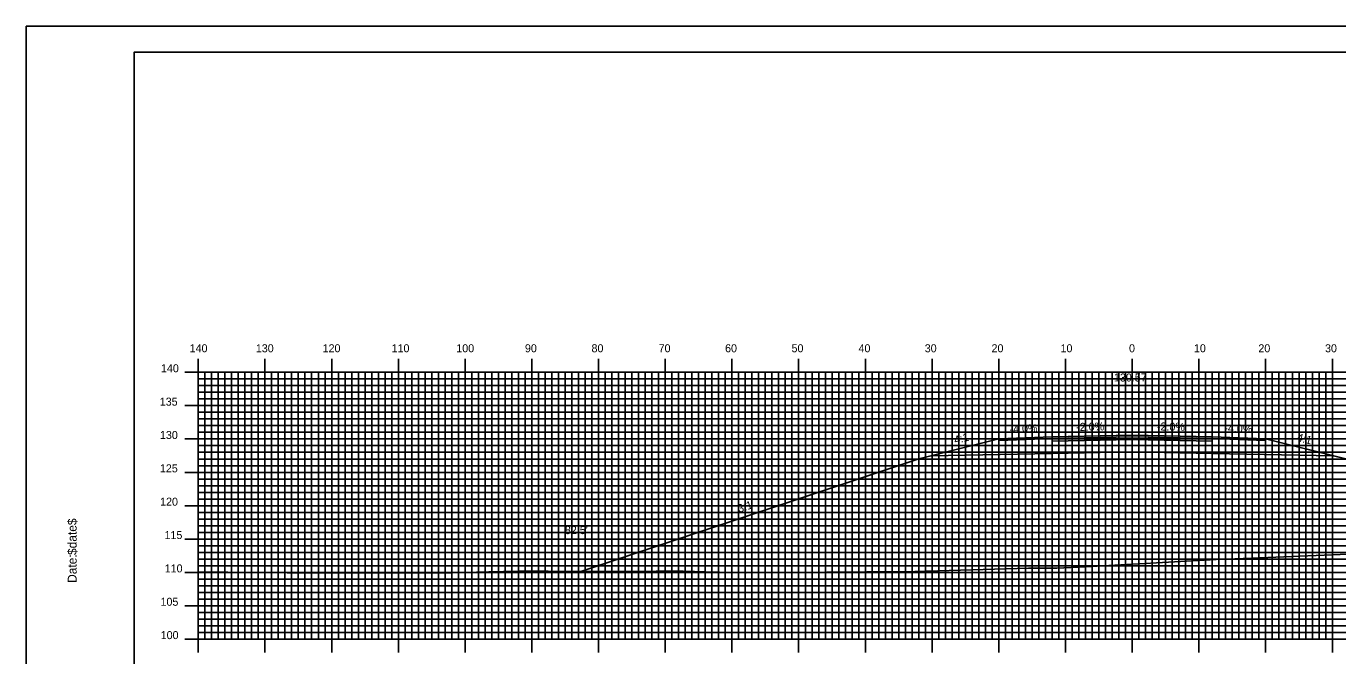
# Model space of a CAD drawing. Extents: x 1781860 to 1782203, y 442591 to 442811.
# Drawn here: x 1781860.1 to 1782056.7, y 442716.2 to 442810.5 of the extents above; entities that cross this region are included whole.
import ezdxf

# ---------------------------------------------------------------- set-up
doc = ezdxf.new("R2010")
doc.units = 0
for name, color, linetype in [('ANNOTATION', 7, 'Continuous'), ('BORDER', 7, 'Continuous'), ('D_Roadway_Centerline', 7, 'Continuous'), ('D_Roadway_Centerline_Text', 7, 'Continuous'), ('D_Roadway_Edge_Shoulder', 7, 'Continuous'), ('D_Roadway_Edge_TW', 7, 'Continuous'), ('D_Roadway_Pavement', 7, 'Continuous'), ('D_Roadway_SlopeLines', 7, 'Continuous'), ('D_Roadway_SubGrade', 7, 'Continuous'), ('D_Text_Standard', 7, 'Continuous'), ('H_V ANNOTATION', 7, 'Continuous'), ('MAJOR', 7, 'Continuous'), ('MINOR', 7, 'Continuous'), ('PLOT BOUNDARY', 7, 'Continuous'), ('S_Roadway_Centerline', 7, 'Continuous')]:
    doc.layers.add(name, color=color, linetype=linetype)

msp = doc.modelspace()

# ---------------------------------------------------------------- linework, layer by layer
at = {"layer": 'BORDER'}
msp.add_lwpolyline([(1781876.32, 442596.67), (1782196.32, 442596.67), (1782196.32, 442806.67), (1781876.32, 442806.67)], close=True, dxfattribs=at)
at = {"layer": 'D_Roadway_Centerline'}
msp.add_lwpolyline([(1781943.4, 442728.84), (1781993.92, 442745.68), (1781995.75, 442746.13), (1782005.92, 442748.68), (1782013.92, 442749), (1782025.92, 442749.24), (1782037.92, 442749), (1782045.92, 442748.68), (1782056.09, 442746.13), (1782057.92, 442745.68), (1782095.42, 442733.18)], dxfattribs=at)
at = {"layer": 'D_Roadway_Edge_Shoulder'}
for points in [[(1782013.92, 442749), (1782005.92, 442748.68), (1782005.92, 442748.43), (1782013.92, 442748.75)], [(1782037.92, 442749), (1782045.92, 442748.68), (1782045.92, 442748.43), (1782037.92, 442748.75)]]:
    msp.add_lwpolyline(points, close=True, dxfattribs=at)
at = {"layer": 'D_Roadway_Edge_TW'}
msp.add_lwpolyline([(1782013.92, 442748.75), (1782013.92, 442749), (1782025.92, 442749.24), (1782037.92, 442749), (1782037.92, 442748.75), (1782025.92, 442748.99)], close=True, dxfattribs=at)
at = {"layer": 'D_Roadway_Pavement'}
msp.add_lwpolyline([(1782013.92, 442748.33), (1782013.92, 442748.75), (1782025.92, 442748.99), (1782037.92, 442748.75), (1782037.92, 442748.33), (1782025.92, 442748.57)], close=True, dxfattribs=at)
at = {"layer": 'D_Roadway_SlopeLines'}
for points in [[(1782005.92, 442748.68), (1781993.92, 442745.68), (1781943.4, 442728.84)], [(1782045.92, 442748.68), (1782057.92, 442745.68), (1782095.42, 442733.18)]]:
    msp.add_lwpolyline(points, dxfattribs=at)
at = {"layer": 'D_Roadway_SubGrade'}
msp.add_lwpolyline([(1782013.92, 442746.5), (1781995.75, 442746.13), (1782005.92, 442748.68), (1782005.92, 442748.43), (1782013.92, 442748.75), (1782025.92, 442748.99), (1782037.92, 442748.75), (1782045.92, 442748.43), (1782045.92, 442748.68), (1782056.09, 442746.13), (1782037.92, 442746.5), (1782025.92, 442746.74)], close=True, dxfattribs=at)
at = {"layer": 'MAJOR'}
for p, q in [((1781885.92, 442760.67), (1781885.92, 442758.67)), ((1781895.92, 442760.67), (1781895.92, 442758.67)), ((1781905.92, 442760.67), (1781905.92, 442758.67)), ((1781915.92, 442760.67), (1781915.92, 442758.67)), ((1781925.92, 442760.67), (1781925.92, 442758.67)), ((1781935.92, 442760.67), (1781935.92, 442758.67)), ((1781945.92, 442760.67), (1781945.92, 442758.67)), ((1781955.92, 442760.67), (1781955.92, 442758.67)), ((1781965.92, 442760.67), (1781965.92, 442758.67)), ((1781975.92, 442760.67), (1781975.92, 442758.67)), ((1781985.92, 442760.67), (1781985.92, 442758.67)), ((1781995.92, 442760.67), (1781995.92, 442758.67)), ((1782005.92, 442760.67), (1782005.92, 442758.67)), ((1782015.92, 442760.67), (1782015.92, 442758.67)), ((1782025.92, 442760.67), (1782025.92, 442758.67)), ((1782035.92, 442760.67), (1782035.92, 442758.67)), ((1782045.92, 442760.67), (1782045.92, 442758.67)), ((1782055.92, 442760.67), (1782055.92, 442758.67)), ((1781883.92, 442758.67), (1781885.92, 442758.67)), ((1781885.92, 442758.67), (1782165.92, 442758.67)), ((1781885.92, 442718.67), (1781885.92, 442758.67)), ((1781885.92, 442718.67), (1781885.92, 442758.67)), ((1781885.92, 442758.67), (1782165.92, 442758.67)), ((1781895.92, 442718.67), (1781895.92, 442758.67)), ((1781905.92, 442718.67), (1781905.92, 442758.67)), ((1781915.92, 442718.67), (1781915.92, 442758.67)), ((1781925.92, 442718.67), (1781925.92, 442758.67)), ((1781935.92, 442718.67), (1781935.92, 442758.67)), ((1781945.92, 442718.67), (1781945.92, 442758.67)), ((1781955.92, 442718.67), (1781955.92, 442758.67)), ((1781965.92, 442718.67), (1781965.92, 442758.67)), ((1781975.92, 442718.67), (1781975.92, 442758.67)), ((1781985.92, 442718.67), (1781985.92, 442758.67)), ((1781995.92, 442718.67), (1781995.92, 442758.67)), ((1782005.92, 442718.67), (1782005.92, 442758.67)), ((1782015.92, 442718.67), (1782015.92, 442758.67)), ((1782025.92, 442718.67), (1782025.92, 442758.67)), ((1782035.92, 442718.67), (1782035.92, 442758.67)), ((1782045.92, 442718.67), (1782045.92, 442758.67)), ((1782055.92, 442718.67), (1782055.92, 442758.67)), ((1781883.92, 442753.67), (1781885.92, 442753.67)), ((1781885.92, 442753.67), (1782165.92, 442753.67)), ((1781883.92, 442748.67), (1781885.92, 442748.67)), ((1781885.92, 442748.67), (1782165.92, 442748.67)), ((1781883.92, 442743.67), (1781885.92, 442743.67)), ((1781885.92, 442743.67), (1782165.92, 442743.67)), ((1781883.92, 442738.67), (1781885.92, 442738.67)), ((1781885.92, 442738.67), (1782165.92, 442738.67)), ((1781883.92, 442733.67), (1781885.92, 442733.67)), ((1781885.92, 442733.67), (1782165.92, 442733.67)), ((1781883.92, 442728.67), (1781885.92, 442728.67)), ((1781885.92, 442728.67), (1782165.92, 442728.67)), ((1781883.92, 442723.67), (1781885.92, 442723.67)), ((1781885.92, 442723.67), (1782165.92, 442723.67)), ((1781883.92, 442718.67), (1781885.92, 442718.67)), ((1781885.92, 442718.67), (1782165.92, 442718.67)), ((1781885.92, 442718.67), (1782165.92, 442718.67)), ((1781885.92, 442716.66), (1781885.92, 442718.67)), ((1781895.92, 442716.66), (1781895.92, 442718.67)), ((1781905.92, 442716.66), (1781905.92, 442718.67)), ((1781915.92, 442716.66), (1781915.92, 442718.67)), ((1781925.92, 442716.66), (1781925.92, 442718.67)), ((1781935.92, 442716.66), (1781935.92, 442718.67)), ((1781945.92, 442716.66), (1781945.92, 442718.67)), ((1781955.92, 442716.66), (1781955.92, 442718.67)), ((1781965.92, 442716.66), (1781965.92, 442718.67)), ((1781975.92, 442716.66), (1781975.92, 442718.67)), ((1781985.92, 442716.66), (1781985.92, 442718.67)), ((1781995.92, 442716.66), (1781995.92, 442718.67)), ((1782005.92, 442716.66), (1782005.92, 442718.67)), ((1782015.92, 442716.66), (1782015.92, 442718.67)), ((1782025.92, 442716.66), (1782025.92, 442718.67)), ((1782035.92, 442716.66), (1782035.92, 442718.67)), ((1782045.92, 442716.66), (1782045.92, 442718.67)), ((1782055.92, 442716.66), (1782055.92, 442718.67))]:
    msp.add_line(p, q, dxfattribs=at)
at = {"layer": 'MINOR'}
for p, q in [((1781885.92, 442757.67), (1782165.92, 442757.67)), ((1781885.92, 442757.67), (1781887.92, 442757.67)), ((1781886.92, 442718.67), (1781886.92, 442758.67)), ((1781887.92, 442718.67), (1781887.92, 442758.67)), ((1781888.92, 442718.67), (1781888.92, 442758.67)), ((1781889.92, 442718.67), (1781889.92, 442758.67)), ((1781890.92, 442718.67), (1781890.92, 442758.67)), ((1781891.92, 442718.67), (1781891.92, 442758.67)), ((1781892.92, 442718.67), (1781892.92, 442758.67)), ((1781893.92, 442718.67), (1781893.92, 442758.67)), ((1781894.92, 442718.67), (1781894.92, 442758.67)), ((1781896.92, 442718.67), (1781896.92, 442758.67)), ((1781897.92, 442718.67), (1781897.92, 442758.67)), ((1781898.92, 442718.67), (1781898.92, 442758.67)), ((1781899.92, 442718.67), (1781899.92, 442758.67)), ((1781900.92, 442718.67), (1781900.92, 442758.67)), ((1781901.92, 442718.67), (1781901.92, 442758.67)), ((1781902.92, 442718.67), (1781902.92, 442758.67)), ((1781903.92, 442718.67), (1781903.92, 442758.67)), ((1781904.92, 442718.67), (1781904.92, 442758.67)), ((1781906.92, 442718.67), (1781906.92, 442758.67)), ((1781907.92, 442718.67), (1781907.92, 442758.67)), ((1781908.92, 442718.67), (1781908.92, 442758.67)), ((1781909.92, 442718.67), (1781909.92, 442758.67)), ((1781910.92, 442718.67), (1781910.92, 442758.67)), ((1781911.92, 442718.67), (1781911.92, 442758.67)), ((1781912.92, 442718.67), (1781912.92, 442758.67)), ((1781913.92, 442718.67), (1781913.92, 442758.67)), ((1781914.92, 442718.67), (1781914.92, 442758.67)), ((1781916.92, 442718.67), (1781916.92, 442758.67)), ((1781917.92, 442718.67), (1781917.92, 442758.67)), ((1781918.92, 442718.67), (1781918.92, 442758.67)), ((1781919.92, 442718.67), (1781919.92, 442758.67)), ((1781920.92, 442718.67), (1781920.92, 442758.67)), ((1781921.92, 442718.67), (1781921.92, 442758.67)), ((1781922.92, 442718.67), (1781922.92, 442758.67)), ((1781923.92, 442718.67), (1781923.92, 442758.67)), ((1781924.92, 442718.67), (1781924.92, 442758.67)), ((1781926.92, 442718.67), (1781926.92, 442758.67)), ((1781927.92, 442718.67), (1781927.92, 442758.67)), ((1781928.92, 442718.67), (1781928.92, 442758.67)), ((1781929.92, 442718.67), (1781929.92, 442758.67)), ((1781930.92, 442718.67), (1781930.92, 442758.67)), ((1781931.92, 442718.67), (1781931.92, 442758.67)), ((1781932.92, 442718.67), (1781932.92, 442758.67)), ((1781933.92, 442718.67), (1781933.92, 442758.67)), ((1781934.92, 442718.67), (1781934.92, 442758.67)), ((1781936.92, 442718.67), (1781936.92, 442758.67)), ((1781937.92, 442718.67), (1781937.92, 442758.67)), ((1781938.92, 442718.67), (1781938.92, 442758.67)), ((1781939.92, 442718.67), (1781939.92, 442758.67)), ((1781940.92, 442718.67), (1781940.92, 442758.67)), ((1781941.92, 442718.67), (1781941.92, 442758.67)), ((1781942.92, 442718.67), (1781942.92, 442758.67)), ((1781943.92, 442718.67), (1781943.92, 442758.67)), ((1781944.92, 442718.67), (1781944.92, 442758.67)), ((1781946.92, 442718.67), (1781946.92, 442758.67)), ((1781947.92, 442718.67), (1781947.92, 442758.67)), ((1781948.92, 442718.67), (1781948.92, 442758.67)), ((1781949.92, 442718.67), (1781949.92, 442758.67)), ((1781950.92, 442718.67), (1781950.92, 442758.67)), ((1781951.92, 442718.67), (1781951.92, 442758.67)), ((1781952.92, 442718.67), (1781952.92, 442758.67)), ((1781953.92, 442718.67), (1781953.92, 442758.67)), ((1781954.92, 442718.67), (1781954.92, 442758.67)), ((1781956.92, 442718.67), (1781956.92, 442758.67)), ((1781957.92, 442718.67), (1781957.92, 442758.67)), ((1781958.92, 442718.67), (1781958.92, 442758.67)), ((1781959.92, 442718.67), (1781959.92, 442758.67)), ((1781960.92, 442718.67), (1781960.92, 442758.67)), ((1781961.92, 442718.67), (1781961.92, 442758.67)), ((1781962.92, 442718.67), (1781962.92, 442758.67)), ((1781963.92, 442718.67), (1781963.92, 442758.67)), ((1781964.92, 442718.67), (1781964.92, 442758.67)), ((1781966.92, 442718.67), (1781966.92, 442758.67)), ((1781967.92, 442718.67), (1781967.92, 442758.67)), ((1781968.92, 442718.67), (1781968.92, 442758.67)), ((1781969.92, 442718.67), (1781969.92, 442758.67)), ((1781970.92, 442718.67), (1781970.92, 442758.67)), ((1781971.92, 442718.67), (1781971.92, 442758.67)), ((1781972.92, 442718.67), (1781972.92, 442758.67)), ((1781973.92, 442718.67), (1781973.92, 442758.67)), ((1781974.92, 442718.67), (1781974.92, 442758.67)), ((1781976.92, 442718.67), (1781976.92, 442758.67)), ((1781977.92, 442718.67), (1781977.92, 442758.67)), ((1781978.92, 442718.67), (1781978.92, 442758.67)), ((1781979.92, 442718.67), (1781979.92, 442758.67)), ((1781980.92, 442718.67), (1781980.92, 442758.67)), ((1781981.92, 442718.67), (1781981.92, 442758.67)), ((1781982.92, 442718.67), (1781982.92, 442758.67)), ((1781983.92, 442718.67), (1781983.92, 442758.67)), ((1781984.92, 442718.67), (1781984.92, 442758.67)), ((1781986.92, 442718.67), (1781986.92, 442758.67)), ((1781987.92, 442718.67), (1781987.92, 442758.67)), ((1781988.92, 442718.67), (1781988.92, 442758.67)), ((1781989.92, 442718.67), (1781989.92, 442758.67)), ((1781990.92, 442718.67), (1781990.92, 442758.67)), ((1781991.92, 442718.67), (1781991.92, 442758.67)), ((1781992.92, 442718.67), (1781992.92, 442758.67)), ((1781993.92, 442718.67), (1781993.92, 442758.67)), ((1781994.92, 442718.67), (1781994.92, 442758.67)), ((1781996.92, 442718.67), (1781996.92, 442758.67)), ((1781997.92, 442718.67), (1781997.92, 442758.67)), ((1781998.92, 442718.67), (1781998.92, 442758.67)), ((1781999.92, 442718.67), (1781999.92, 442758.67)), ((1782000.92, 442718.67), (1782000.92, 442758.67)), ((1782001.92, 442718.67), (1782001.92, 442758.67)), ((1782002.92, 442718.67), (1782002.92, 442758.67)), ((1782003.92, 442718.67), (1782003.92, 442758.67)), ((1782004.92, 442718.67), (1782004.92, 442758.67)), ((1782006.92, 442718.67), (1782006.92, 442758.67)), ((1782007.92, 442718.67), (1782007.92, 442758.67)), ((1782008.92, 442718.67), (1782008.92, 442758.67)), ((1782009.92, 442718.67), (1782009.92, 442758.67)), ((1782010.92, 442718.67), (1782010.92, 442758.67)), ((1782011.92, 442718.67), (1782011.92, 442758.67)), ((1782012.92, 442718.67), (1782012.92, 442758.67)), ((1782013.92, 442718.67), (1782013.92, 442758.67)), ((1782014.92, 442718.67), (1782014.92, 442758.67)), ((1782016.92, 442718.67), (1782016.92, 442758.67)), ((1782017.92, 442718.67), (1782017.92, 442758.67)), ((1782018.92, 442718.67), (1782018.92, 442758.67)), ((1782019.92, 442718.67), (1782019.92, 442758.67)), ((1782020.92, 442718.67), (1782020.92, 442758.67)), ((1782021.92, 442718.67), (1782021.92, 442758.67)), ((1782022.92, 442718.67), (1782022.92, 442758.67)), ((1782023.92, 442718.67), (1782023.92, 442758.67)), ((1782024.92, 442718.67), (1782024.92, 442758.67)), ((1782026.92, 442718.67), (1782026.92, 442758.67)), ((1782027.92, 442718.67), (1782027.92, 442758.67)), ((1782028.92, 442718.67), (1782028.92, 442758.67)), ((1782029.92, 442718.67), (1782029.92, 442758.67)), ((1782030.92, 442718.67), (1782030.92, 442758.67)), ((1782031.92, 442718.67), (1782031.92, 442758.67)), ((1782032.92, 442718.67), (1782032.92, 442758.67)), ((1782033.92, 442718.67), (1782033.92, 442758.67)), ((1782034.92, 442718.67), (1782034.92, 442758.67)), ((1782036.92, 442718.67), (1782036.92, 442758.67)), ((1782037.92, 442718.67), (1782037.92, 442758.67)), ((1782038.92, 442718.67), (1782038.92, 442758.67)), ((1782039.92, 442718.67), (1782039.92, 442758.67)), ((1782040.92, 442718.67), (1782040.92, 442758.67)), ((1782041.92, 442718.67), (1782041.92, 442758.67)), ((1782042.92, 442718.67), (1782042.92, 442758.67)), ((1782043.92, 442718.67), (1782043.92, 442758.67)), ((1782044.92, 442718.67), (1782044.92, 442758.67)), ((1782046.92, 442718.67), (1782046.92, 442758.67)), ((1782047.92, 442718.67), (1782047.92, 442758.67)), ((1782048.92, 442718.67), (1782048.92, 442758.67)), ((1782049.92, 442718.67), (1782049.92, 442758.67)), ((1782050.92, 442718.67), (1782050.92, 442758.67)), ((1782051.92, 442718.67), (1782051.92, 442758.67)), ((1782052.92, 442718.67), (1782052.92, 442758.67)), ((1782053.92, 442718.67), (1782053.92, 442758.67)), ((1782054.92, 442718.67), (1782054.92, 442758.67)), ((1781885.92, 442756.67), (1782165.92, 442756.67)), ((1781885.92, 442756.67), (1781887.92, 442756.67)), ((1781885.92, 442755.67), (1782165.92, 442755.67)), ((1781885.92, 442755.67), (1781887.92, 442755.67)), ((1781885.92, 442754.67), (1782165.92, 442754.67)), ((1781885.92, 442754.67), (1781887.92, 442754.67)), ((1781885.92, 442752.67), (1782165.92, 442752.67)), ((1781885.92, 442752.67), (1781887.92, 442752.67)), ((1781885.92, 442751.67), (1782165.92, 442751.67)), ((1781885.92, 442751.67), (1781887.92, 442751.67)), ((1781885.92, 442750.67), (1782165.92, 442750.67)), ((1781885.92, 442750.67), (1781887.92, 442750.67)), ((1781885.92, 442749.67), (1782165.92, 442749.67)), ((1781885.92, 442749.67), (1781887.92, 442749.67)), ((1781885.92, 442747.67), (1782165.92, 442747.67)), ((1781885.92, 442747.67), (1781887.92, 442747.67)), ((1781885.92, 442746.67), (1782165.92, 442746.67)), ((1781885.92, 442746.67), (1781887.92, 442746.67)), ((1781885.92, 442745.67), (1782165.92, 442745.67)), ((1781885.92, 442745.67), (1781887.92, 442745.67)), ((1781885.92, 442744.67), (1782165.92, 442744.67)), ((1781885.92, 442744.67), (1781887.92, 442744.67)), ((1781885.92, 442742.67), (1782165.92, 442742.67)), ((1781885.92, 442742.67), (1781887.92, 442742.67)), ((1781885.92, 442741.67), (1782165.92, 442741.67)), ((1781885.92, 442741.67), (1781887.92, 442741.67)), ((1781885.92, 442740.67), (1782165.92, 442740.67)), ((1781885.92, 442740.67), (1781887.92, 442740.67)), ((1781885.92, 442739.67), (1782165.92, 442739.67)), ((1781885.92, 442739.67), (1781887.92, 442739.67)), ((1781885.92, 442737.67), (1782165.92, 442737.67)), ((1781885.92, 442737.67), (1781887.92, 442737.67)), ((1781885.92, 442736.67), (1782165.92, 442736.67)), ((1781885.92, 442736.67), (1781887.92, 442736.67)), ((1781885.92, 442735.67), (1782165.92, 442735.67)), ((1781885.92, 442735.67), (1781887.92, 442735.67)), ((1781885.92, 442734.67), (1782165.92, 442734.67)), ((1781885.92, 442734.67), (1781887.92, 442734.67)), ((1781885.92, 442732.67), (1782165.92, 442732.67)), ((1781885.92, 442732.67), (1781887.92, 442732.67)), ((1781885.92, 442731.67), (1782165.92, 442731.67)), ((1781885.92, 442731.67), (1781887.92, 442731.67)), ((1781885.92, 442730.67), (1782165.92, 442730.67)), ((1781885.92, 442730.67), (1781887.92, 442730.67)), ((1781885.92, 442729.67), (1782165.92, 442729.67)), ((1781885.92, 442729.67), (1781887.92, 442729.67)), ((1781885.92, 442727.67), (1782165.92, 442727.67)), ((1781885.92, 442727.67), (1781887.92, 442727.67)), ((1781885.92, 442726.67), (1782165.92, 442726.67)), ((1781885.92, 442726.67), (1781887.92, 442726.67)), ((1781885.92, 442725.67), (1782165.92, 442725.67)), ((1781885.92, 442725.67), (1781887.92, 442725.67)), ((1781885.92, 442724.67), (1782165.92, 442724.67)), ((1781885.92, 442724.67), (1781887.92, 442724.67)), ((1781885.92, 442722.67), (1782165.92, 442722.67)), ((1781885.92, 442722.67), (1781887.92, 442722.67)), ((1781885.92, 442721.67), (1782165.92, 442721.67)), ((1781885.92, 442721.67), (1781887.92, 442721.67)), ((1781885.92, 442720.67), (1782165.92, 442720.67)), ((1781885.92, 442720.67), (1781887.92, 442720.67)), ((1781885.92, 442719.67), (1782165.92, 442719.67)), ((1781885.92, 442719.67), (1781887.92, 442719.67))]:
    msp.add_line(p, q, dxfattribs=at)
at = {"layer": 'PLOT BOUNDARY'}
msp.add_lwpolyline([(1781860.13, 442590.55), (1782200.13, 442590.55), (1782200.13, 442810.55), (1781860.13, 442810.55)], close=True, dxfattribs=at)
at = {"layer": 'S_Roadway_Centerline'}
msp.add_lwpolyline([(1781885.92, 442728.76), (1781899.24, 442728.59), (1781906.31, 442728.62), (1781922.05, 442728.54), (1781929.48, 442728.75), (1781933.88, 442728.84), (1781938.39, 442728.85), (1781952.2, 442728.82), (1781956.92, 442728.89), (1781961.99, 442728.76), (1781968.13, 442728.6), (1781986.15, 442728.76), (1781991.63, 442728.75), (1781996.78, 442728.9), (1782010.38, 442729.29), (1782014.62, 442729.32), (1782018.88, 442729.5), (1782038.48, 442730.62), (1782039.98, 442730.66), (1782043.87, 442730.79), (1782061.88, 442731.55)], dxfattribs=at)

# ---------------------------------------------------------------- texts
at = {"layer": 'ANNOTATION'}
for s, rotation, p in [('-2.0%', 1.1458, (1782017.53, 442749.87)), ('-2.0%', 358.8542, (1782029.61, 442749.96)), ('4:1', 14.0362, (1781999.37, 442747.9)), ('-4.0%', 2.2906, (1782007.55, 442749.54)), ('-4.0%', 357.7094, (1782039.71, 442749.73)), ('4:1', 345.9638, (1782050.51, 442748.39)), ('3:1', 18.4348, (1781967, 442737.61))]:
    msp.add_text(s, height=1.2, rotation=rotation, dxfattribs=at).set_placement(p)
at = {"layer": 'BORDER'}
for s, p in [('$date$', (1781867.69, 442731.28)), ('Date:', (1781867.69, 442727.1))]:
    msp.add_text(s, height=1.339, rotation=90, dxfattribs=at).set_placement(p)
at = {"layer": 'D_Roadway_Centerline'}
for s, p in [('C', (1782025.92, 442749.24)), ('L', (1782025.92, 442749.23))]:
    msp.add_text(s, height=0.0146, dxfattribs=at).set_placement(p)
at = {"layer": 'D_Roadway_Centerline_Text'}
msp.add_text('130.57', height=1.2, dxfattribs=at).set_placement((1782023.18, 442757.29))
at = {"layer": 'D_Text_Standard'}
msp.add_text("82.5'", height=1.2, dxfattribs=at).set_placement((1781940.88, 442734.41))
at = {"layer": 'H_V ANNOTATION'}
for s, p in [('140', (1781884.63, 442761.67)), ('130', (1781894.55, 442761.67)), ('120', (1781904.56, 442761.67)), ('110', (1781914.9, 442761.67)), ('100', (1781924.6, 442761.67)), ('90', (1781934.89, 442761.67)), ('80', (1781944.87, 442761.67)), ('70', (1781954.93, 442761.67)), ('60', (1781964.89, 442761.67)), ('50', (1781974.85, 442761.67)), ('40', (1781984.89, 442761.67)), ('30', (1781994.82, 442761.67)), ('20', (1782004.83, 442761.67)), ('10', (1782015.17, 442761.67)), ('0', (1782025.44, 442761.67)), ('10', (1782035.17, 442761.67)), ('20', (1782044.83, 442761.67)), ('30', (1782054.82, 442761.67)), ('140', (1781880.33, 442758.67)), ('135', (1781880.15, 442753.67)), ('130', (1781880.18, 442748.67)), ('125', (1781880.17, 442743.67)), ('120', (1781880.2, 442738.67)), ('115', (1781880.86, 442733.67)), ('110', (1781880.89, 442728.67)), ('105', (1781880.26, 442723.67)), ('100', (1781880.29, 442718.67))]:
    msp.add_text(s, height=1.2, dxfattribs=at).set_placement(p)
at = {"layer": 'MAJOR'}
msp.add_text('-', height=0.012, dxfattribs=at).set_placement((1781885.91, 442718.67))

doc.saveas('drawing.dxf')
